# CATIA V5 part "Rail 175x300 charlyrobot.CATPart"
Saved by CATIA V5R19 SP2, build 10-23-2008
Part number: Rail 175x300 charlyrobot
Bounding box of the stored display mesh (mm): x 0 to 300, y 0 to 30, z 0 to 175
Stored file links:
  Z:\fausse table rondelle-20220905T211342Z-001\fausse table rondelle\Rail 175x300 charlyrobot.CATPart
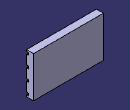
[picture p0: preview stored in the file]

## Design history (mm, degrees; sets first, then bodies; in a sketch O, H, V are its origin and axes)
AxisSystem1: origin (0, 0, 0), X (1, 0, 0), Y (0, 1, 0), Z (0, 0, 1)
Body1 (main body)
  Sketch1 on YZ plane of AxisSystem1, origin (0, 0, 0), H (0, 1, 0), V (0, 0, 1)
    line L1 (0, 0) -> (30, 0)
    line L2 (30, 0) -> (30, 175)
    line L3 (30, 175) -> (0, 175)
    line L4 (0, 175) -> (0, 0)
    distance L4 L2 = 30
    distance L3 L1 = 175
    horizontal: L1 H, L3 H
    vertical: L2 V, L4 V
  Pad1: profile Sketch1, direction (1, 0, 0), length 300
  Sketch2 on YZ plane of AxisSystem1, origin (0, 0, 0), H (0, 1, 0), V (0, 0, 1)
    point P1 (5.125, 12.5)
    line L1 (7.75, 17.75) -> (7.75, 7.25)
    line L2 (7.75, 7.25) -> (2.5, 7.25)
    line L3 (2.5, 7.25) -> (2.5, 9.25)
    line L4 (2.5, 17.75) -> (7.75, 17.75)
    point P6 (1.3125, 12.5)
    construction line L5 (5.125, 9.25) -> (5.125, 15.75)
    line L6 (2.5, 15.75) -> (-2.5, 15.75)
    line L7 (-2.5, 15.75) -> (-2.5, 9.25)
    line L8 (-2.5, 9.25) -> (2.5, 9.25)
    point P7 (5.125, 9.25)
    point P8 (5.125, 15.75)
    reference intersected line E1 through (0, 0) direction (0, 1) from ZX plane of AxisSystem1
    reference intersected line E2 through (0, 0) direction (-1, 0) from XY plane of AxisSystem1
    line L9 (2.5, 15.75) -> (2.5, 17.75)
    length L1 = 10.5
    length L4 = 5.25
    length L7 = 6.5
    distance L3 L7 = 5
    distance L3 E1 = 2.5
    distance P6 E2 = 12.5
    vertical: L1 V, L3 V, L5 V, L7 V
    horizontal: L2 H, L4 H, L6 H, L8 H
    equidistance: L1 L3 P1, L2 L4 P1, L5 L7 P6, L6 L8 P6
    midpoint: L5 P1
    coincidence: L3 L9, P7 L8, P8 L6
  Pocket1: profile Sketch2, direction (-1, 0, 0), through (limit type 3)
  Sketch3 on ZX plane of AxisSystem1, origin (0, 0, 0), H (0, 0, 1), V (1, 0, 0)
    construction line L1 (12.5, 260) -> (12.5, 300)
    point P2 (12.5, 300)
    line L2 (7.4, 260) -> (7.4, 300)
    line L3 (17.6, 300) -> (17.6, 260)
    arc A1 centre (12.5, 300) radius 5.1 from (7.4, 300) to (17.6, 300) cw
    arc A2 centre (12.5, 260) radius 5.1 from (17.6, 260) to (7.4, 260) cw
    reference intersected line E1 through (0, 0) direction (0, 1) from XY plane of AxisSystem1
    reference intersected line E2 (0, 300) -> (200, 300) from end face of Pad1
    distance L1 L2 = 5.1
    distance L1 E1 = 12.5
    length L1 = 40
    vertical: L1 V
    tangency: A1 L2, A2 L2, A1 L3, A2 L3
    coincidence: P2 E2
  Pocket2: profile Sketch3, direction (0, 1, 0), length 5
  RectPattern1: of Pocket1, Pocket2, direction 1 instances 4, spacing 50, along Z axis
